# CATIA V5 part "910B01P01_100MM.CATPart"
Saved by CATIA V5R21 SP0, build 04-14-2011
Part number: 910B01P01_100MM
Bounding box of the stored display mesh (mm): x -48.8 to 48.8, y -17.69 to 17.7, z -5 to 5
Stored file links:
  C:\Users\ALI OZGUN\Desktop\alhan\910B01P01_100MM.CATPart
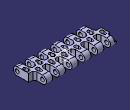
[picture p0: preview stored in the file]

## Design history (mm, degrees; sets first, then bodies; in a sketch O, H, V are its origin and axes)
Body1 (main body)
  Sketch1 on yz-plane, origin (0, 0, 0), H (0, 1, 0), V (0, 0, 1)
    construction line L1 (-12.7, 0) -> (12.7, 0)
    point P1 (-12.7, 0)
    line L2 (-12.7, 5) -> (12.7, 5)
    line L3 (12.7, -5) -> (-12.7, -5)
    arc A1 centre (12.7, 0) radius 5 from (12.7, 5) to (12.7, -5) cw
    arc A2 centre (-12.7, 0) radius 5 from (-12.7, -5) to (-12.7, 5) cw
    circle A3 centre (12.7, 0) radius 2.5
    point P7 (-12.7, 0)
    circle A4 centre (-12.7, 0) radius 2.5
    distance L1 L2 = 5
    radius A3 = 2.5
    length L1 = 25.4
    distance P7 V = 12.7
    coincidence: P1 H
    horizontal: L1 H
    tangency: A1 L2, A2 L2, A1 L3, A2 L3
    symmetry: A3 A4 V
  Pad1: profile Sketch1, direction (1, 0, 0), length 48.8, mirrored extent
  Sketch2 on xy-plane, origin (0, 0, 0), H (1, 0, 0), V (0, 1, 0)
    line L1 (-40.8, 21.9078) -> (-40.8, 5.6641)
    line L2 (-40.8, 5.6641) -> (-38.8, 2.2)
    line L3 (-38.8, 2.2) -> (-34.3, 2.2)
    point P3 (-34.3, 2.2)
    line L4 (-34.3, 2.2) -> (-32.3, 5.6641)
    line L5 (-32.3, 5.6641) -> (-32.3, 21.9078)
    line L6 (-49.05, -18.5853) -> (-49.05, -5.6641)
    line L7 (-49.05, -5.6641) -> (-47.05, -2.2)
    line L8 (-47.05, -2.2) -> (-42.55, -2.2)
    point P7 (-42.55, -2.2)
    line L9 (-42.55, -2.2) -> (-40.55, -5.6641)
    line L10 (-40.55, -5.6641) -> (-40.55, -18.5853)
    reference projected line E1 (-48.8, 12.7) -> (-48.8, -12.7) from edge [start face of Pad1 | face of Pad1 from Sketch1.L2]
    reference projected line E2 (-48.8, 12.7) -> (-48.8, -12.7) from edge [start face of Pad1 | face of Pad1 from Sketch1.L2]
    construction line L11 (-44.8, -40.4005) -> (-44.8, 18.5197)
    axis line L12 (-36.55, 43.4801) -> (-36.55, -9.4971)
    reference projected line E3 through (0, -12.7) direction (1, 0) from axis of face of Pad1 from Sketch1.A2
    reference projected line E4 through (0, 12.7) direction (1, 0) from axis of face of Pad1 from Sketch1.A1
    line L13 (-40.8, 21.9078) -> (-32.3, 21.9078)
    line L14 (-49.05, -18.5853) -> (-40.55, -18.5853)
    distance L1 L5 = 8.5
    distance L1 E1 = 8
    distance L6 L10 = 8.5
    distance L6 E2 = 0.25
    distance L11 L10 = 4.25
    distance L12 L5 = 4.25
    angle L7 L6 = 150
    angle L9 L10 = 150
    distance L8 E3 = 10.5
    length L8 = 4.5
    distance P7 L11 = 2.25
    length L3 = 4.5
    distance P3 L12 = 2.25
    angle L2 L1 = 150
    angle L4 L5 = 150
    distance L3 E4 = 10.5
    vertical: L1 V, L5 V, L6 V, L10 V, L11 V, L12 V
    horizontal: L3 H, L8 H, L13 H, L14 H
  Pocket1: profile Sketch2, direction (0, 0, -1), length 24.25, mirrored extent
  RectPattern1: of Pocket1, direction 1 instances 6, spacing 16.5, along axis of face of Pad1 from Sketch1.A2
  RemoveFace1: RemoveFaces (face of Pocket1 from Sketch2.L7; face of RectPattern1)
  Sketch3 on xy-plane, origin (0, 0, 0), H (1, 0, 0), V (0, 1, 0)
    arc A1 centre (-44.8, 2.7) radius 2.4 from (-47.1385, 3.24) to (-42.4615, 3.24) ccw
    point P1 (-44.8, 2.7)
    reference projected line E1 (-48.8, 12.7) -> (-48.8, -12.7) from edge [start face of Pad1 | face of Pad1 from Sketch1.L2]
    reference projected line E2 through (0, 12.7) direction (1, 0) from axis of face of Pad1 from Sketch1.A1
    arc A2 centre (-44.8, 6.7) radius 1.5 from (-43.3385, 7.0375) to (-46.2615, 7.0375) ccw
    point P2 (-44.8, 6.7)
    line L1 (-43.3385, 7.0375) -> (-42.4615, 3.24)
    line L2 (-46.2615, 7.0375) -> (-47.1385, 3.24)
    reference projected line E3 (-48.8, 12.7) -> (-48.8, -12.7) from edge [start face of Pad1 | face of Pad1 from Sketch1.L2]
    point P7 (-36.55, -2.5)
    arc A3 centre (-36.55, -2.5) radius 2.4 from (-38.8885, -3.04) to (-34.2115, -3.04) cw
    arc A4 centre (-36.55, -6.5) radius 1.5 from (-35.0885, -6.8375) to (-38.0115, -6.8375) cw
    line L3 (-35.0885, -6.8375) -> (-34.2115, -3.04)
    line L4 (-38.0115, -6.8375) -> (-38.8885, -3.04)
    reference projected line E4 (-40.55, -12.7) -> (-40.55, -5.6641) from edge [face of Pad1 from Sketch1.L2 | face of Pocket1 from Sketch2.L10]
    radius A1 = 2.4
    distance E1 P1 = 4
    distance P1 E2 = 10
    radius A2 = 1.5
    distance A2 A1 = 7.9
    distance P2 E3 = 4
    distance P7 E4 = 4
    distance P7 P1 V = 5.2
    tangency: L1 A2, L1 A1, L2 A2, L2 A1
  Pocket2: profile Sketch3, direction (0, 0, -1), length 24.25, mirrored extent
  RectPattern2: of Pocket2, direction 1 instances 6, spacing 16.5, along axis of face of Pad1 from Sketch1.A2
  Sketch4 on start face of Pad1, origin (-48.8, 0, 0), H (0, -1, 0), V (0, 0, 1)
    arc A1 centre (-12.7, 0) radius 3.95 from (-16.65, 0) to (-8.75, 0) ccw
    point P1 (-12.7, 0)
    reference projected circle E1 centre (-12.7, 0) radius 2.5 from edge [face of Pad1 from Sketch1.A3 | start face of Pad1]
    line L1 (-8.75, 0) -> (-8.75, 11.0169)
    point P2 (-8.75, 0)
    line L2 (-16.65, 0) -> (-24.5458, 0)
    point P4 (-16.65, 0)
    point P6 (-16.65, 0)
    point P7 (-8.75, 0)
    radius A1 = 3.95
    concentricity: P1 E1
    coincidence: P2 A1, P2 H, P4 A1, P4 H, L1 P7, L2 P6, P2 P7, P4 P6
    tangency: L1 A1
    horizontal: L2 H
  Pocket3: profile Sketch4, direction (1, 0, 0), length 2.8
Body2
  Solid1: linked copy from another document
  Translate1: Direction zx-plane, Length 25.2, ToTransfor Solid1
